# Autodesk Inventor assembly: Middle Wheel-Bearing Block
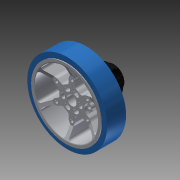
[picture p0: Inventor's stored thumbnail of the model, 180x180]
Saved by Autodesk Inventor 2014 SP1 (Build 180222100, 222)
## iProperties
Created: 2014-09
Part Number: Middle Wheel-Bearing Block
Document SubType Name: Assembly
Designer: Michael
Author: Michael
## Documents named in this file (4)
- C:\Users\Michael\Documents\Inventor\6 CIM V2\Middle Wheel-Bearing Block.iam
- C:\Users\Michael\Documents\Inventor\6 CIM V2\217-3634-STEP.ipt
- C:\Users\Michael\Documents\Inventor\6 CIM V2\4 Perf ThruTread 500 Key.ipt
- C:\Users\Michael\Documents\Inventor\6 CIM V2\Blue Nitrile Tread.ipt
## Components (3 placed, 3 different names)
1. 217-3634-STEP:1 — Mate:2, Flush:1
2. 4 Perf ThruTread 500 Key:1 — Mate:1, Mate:3, Flush:1
3. Blue Nitrile Tread:1 — Mate:1, Mate:2, Mate:3
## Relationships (4: Mate 3, Flush 1)
- Mate:1: 4 Perf ThruTread 500 Key:1 ↔ Blue Nitrile Tread:1
- Mate:2: 217-3634-STEP:1 ↔ Blue Nitrile Tread:1
- Mate:3: 4 Perf ThruTread 500 Key:1 ↔ Blue Nitrile Tread:1
- Flush:1: 217-3634-STEP:1 ↔ 4 Perf ThruTread 500 Key:1
